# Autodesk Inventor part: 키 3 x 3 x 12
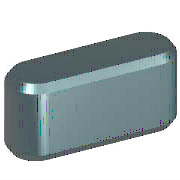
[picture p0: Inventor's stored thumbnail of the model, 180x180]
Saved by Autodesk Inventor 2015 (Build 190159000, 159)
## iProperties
Created: 2012-02
Part Number: 키 3 x 3 x 12
Material: 강철, 연강
Description: 키 및 해당 키홈
Document SubType Name: Modeling
Standard: KS B 1311
Designer: mduedu
Standards Organization: KS
Language: ko-KR
Size Designation: 3 x 3 x 12
Categories: <MemberInstance><Categories><Category DisplayName="샤프트 부품" InternalName="7f7aeb1f-a693-4053-b835-cee3144e0d98" Mnemonic="SHFT"><Category DisplayName="키" Interna
Density: 1 g/cm^3
Appearance: 노란색
IsCustomPart: 1
Author: mduedu
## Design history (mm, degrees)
workplane "Work Plane1"
workplane "Work Plane2"
sketch "스케치1"
  geometry: L1 (1.5, 1.5)-(10.5, 1.5); L2 (10.5, -1.5)-(1.5, -1.5); L3 (0, 9.4)-(0, -7.4) reference; L4 (-5, 0)-(30, 0) reference; L5 (12, 0)-(12, 7); A1 r 1.5 centre (1.5, 0) between (1.5, 1.5) and (1.5, -1.5); A2 r 1.5 centre (10.5, 0) between (10.5, -1.5) and (10.5, 1.5)
  constraints: 6 end point, 5 point on circle, 4 tangent, 3 point on line, 2 centre point, 1 horizontal, 1 parallel, 1 perpendicular
  dimensions: "d0" = 1.5 radius of A1 (= 0.5 x PB); "d13" = 1.5 radius of A2 (= 0.5 x PB); "d14" = 12 distance between parallel lines of L5 L3 (= NLG)
extrude "본체1" new body sketch "스케치1" taper "d3" = 0 deg; stored distance "d4" = 10
workplane "Work Plane3"
body "Solid1"
chamfer "모따기1" distance "d8" = 0.25 (= PHH); stored, may be unused: second distance "d9" = 0.25 (= PHH), angle "d15" = 45 deg
other parameters: "d1" = -1.8 (= -PNT), "d2" = 1.2 (= PH - PNT), "NLG" = 12 [user parameter; used in 3 equation terms], "PB" = 3 [user parameter; used in 2 equation terms], "PNT" = 1.8 [user parameter; used in 2 equation terms], "PH" = 3 [user parameter; used in 1 equation term], "PHH" = 0.25 [user parameter; used in 2 equation terms], "d10" = 0, "d16" = 0, "d17" = 0, "d18" = 0, "WDMIN" = 8 [user parameter], "PLB2" = 12 (= NLG) [user parameter], "PLB1" = 12 (= NLG) [user parameter], "RR" = 0.08 [user parameter], "PUEB" = 1.4 [user parameter]
